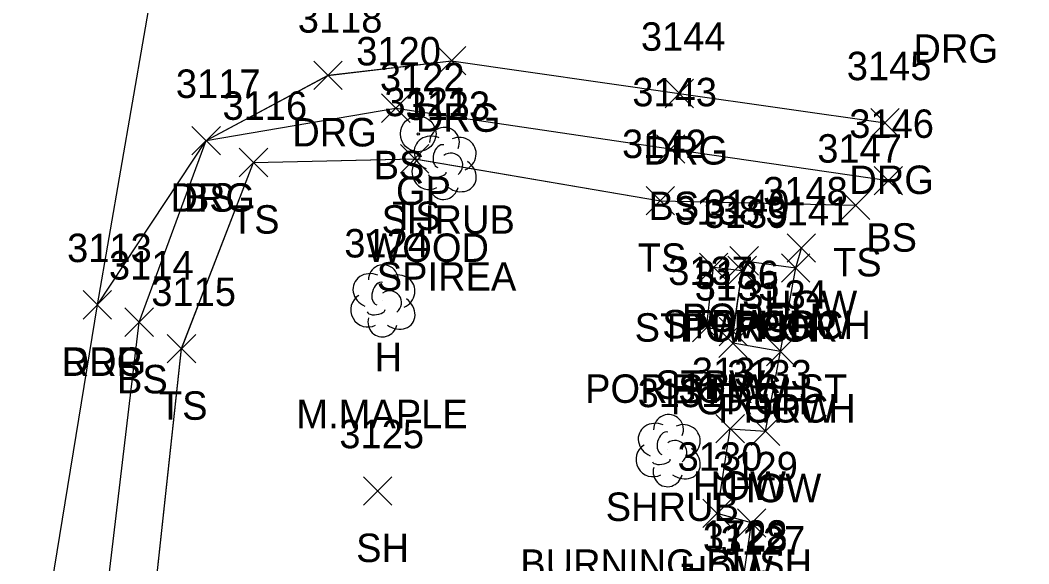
# Model space of a CAD drawing. Extents: x 1554668 to 1563881, y 831386 to 834374.
# Drawn here: x 1562326.2 to 1562397.1, y 833011.6 to 833049.8 of the extents above; entities that cross this region are included whole.
import ezdxf

# ---------------------------------------------------------------- set-up
doc = ezdxf.new("R2010")
doc.units = 0
for name, color, linetype in [('C_I', 7, 'Continuous'), ('L_A', 7, 'Continuous'), ('L_C', 7, 'Continuous'), ('L_I', 7, 'Continuous'), ('L_TIC', 7, 'Continuous'), ('LBC', 7, 'Continuous'), ('LBF', 7, 'Continuous'), ('LELB', 7, 'Continuous'), ('LSH', 7, 'Continuous'), ('LTD', 7, 'Continuous'), ('P_A', 7, 'Continuous'), ('P_I', 7, 'Continuous'), ('P_TIC', 7, 'Continuous'), ('PET', 7, 'Continuous'), ('R_A', 7, 'Continuous'), ('R_C', 7, 'Continuous'), ('R_I', 7, 'Continuous'), ('R_TIC', 7, 'Continuous'), ('RDG', 7, 'Continuous'), ('RGP', 7, 'Continuous')]:
    doc.layers.add(name, color=color, linetype=linetype)

msp = doc.modelspace()

# ---------------------------------------------------------------- linework, layer by layer
at = {"layer": 'L_TIC'}
for points in [[(1562351.645, 833042.623), (1562353.645, 833044.623)], [(1562353.645, 833042.623), (1562351.645, 833044.623)], [(1562338.315, 833040.338), (1562340.315, 833042.338)], [(1562340.315, 833040.338), (1562338.315, 833042.338)], [(1562370.953, 833039.751), (1562372.953, 833041.751)], [(1562372.953, 833039.751), (1562370.953, 833041.751)], [(1562352.966, 833039.056), (1562354.966, 833041.056)], [(1562354.966, 833039.056), (1562352.966, 833041.056)], [(1562341.647, 833038.798), (1562343.647, 833040.798)], [(1562343.647, 833038.798), (1562341.647, 833040.798)], [(1562386.252, 833037.529), (1562388.252, 833039.529)], [(1562388.252, 833037.529), (1562386.252, 833039.529)], [(1562370.232, 833036.114), (1562372.232, 833038.114)], [(1562372.232, 833036.114), (1562370.232, 833038.114)], [(1562383.95, 833035.789), (1562385.95, 833037.789)], [(1562385.95, 833035.789), (1562383.95, 833037.789)], [(1562380.14, 833032.785), (1562382.14, 833034.785)], [(1562382.14, 833032.785), (1562380.14, 833034.785)], [(1562376.122, 833031.884), (1562378.122, 833033.884)], [(1562378.122, 833031.884), (1562376.122, 833033.884)], [(1562373.972, 833031.433), (1562375.972, 833033.433)], [(1562375.972, 833031.433), (1562373.972, 833033.433)], [(1562375.975, 833031.204), (1562377.975, 833033.204)], [(1562377.975, 833031.204), (1562375.975, 833033.204)], [(1562375.975, 833031.204), (1562377.975, 833033.204)], [(1562377.975, 833031.204), (1562375.975, 833033.204)], [(1562379.744, 833031.387), (1562381.744, 833033.387)], [(1562381.744, 833031.387), (1562379.744, 833033.387)], [(1562379.744, 833031.387), (1562381.744, 833033.387)], [(1562381.744, 833031.387), (1562379.744, 833033.387)], [(1562333.613, 833027.571), (1562335.613, 833029.571)], [(1562335.613, 833027.571), (1562333.613, 833029.571)], [(1562373.478, 833027.184), (1562375.478, 833029.184)], [(1562375.478, 833027.184), (1562373.478, 833029.184)], [(1562375.358, 833026.903), (1562377.358, 833028.903)], [(1562377.358, 833026.903), (1562375.358, 833028.903)], [(1562375.358, 833026.903), (1562377.358, 833028.903)], [(1562377.358, 833026.903), (1562375.358, 833028.903)], [(1562336.588, 833025.713), (1562338.588, 833027.713)], [(1562338.588, 833025.713), (1562336.588, 833027.713)], [(1562375.339, 833026.093), (1562377.339, 833028.093)], [(1562377.339, 833026.093), (1562375.339, 833028.093)], [(1562378.681, 833025.516), (1562380.681, 833027.516)], [(1562380.681, 833025.516), (1562378.681, 833027.516)], [(1562378.681, 833025.516), (1562380.681, 833027.516)], [(1562380.681, 833025.516), (1562378.681, 833027.516)], [(1562375.137, 833020.084), (1562377.137, 833022.084)], [(1562377.137, 833020.084), (1562375.137, 833022.084)], [(1562377.615, 833019.915), (1562379.615, 833021.915)], [(1562379.615, 833019.915), (1562377.615, 833021.915)], [(1562350.368, 833015.711), (1562352.368, 833017.711)], [(1562352.368, 833015.711), (1562350.368, 833017.711)], [(1562374.22, 833014.13), (1562376.22, 833016.13)], [(1562376.22, 833014.13), (1562374.22, 833016.13)], [(1562376.642, 833013.459), (1562378.642, 833015.459)], [(1562378.642, 833013.459), (1562376.642, 833015.459)]]:
    msp.add_lwpolyline(points, dxfattribs=at)
at = {"layer": 'LBC'}
for points in [[(1562378.15, 833009.239), (1562376.909, 833009.438), (1562377.643, 833014.459), (1562375.22, 833015.13), (1562376.134, 833021.083), (1562378.615, 833020.915), (1562379.684, 833026.518), (1562380.743, 833032.387), (1562381.143, 833033.787)], [(1562378.15, 833009.239), (1562376.909, 833009.438), (1562377.643, 833014.459), (1562375.22, 833015.13), (1562376.134, 833021.083), (1562378.615, 833020.915), (1562379.684, 833026.518), (1562380.743, 833032.387), (1562381.143, 833033.787)], [(1562378.15, 833009.239), (1562376.909, 833009.438), (1562377.643, 833014.459), (1562375.22, 833015.13), (1562376.134, 833021.083), (1562378.615, 833020.915), (1562379.684, 833026.518), (1562380.743, 833032.387), (1562381.143, 833033.787)], [(1562378.154, 833009.24), (1562376.909, 833009.438), (1562377.642, 833014.459), (1562375.22, 833015.13), (1562376.137, 833021.084), (1562378.615, 833020.915), (1562379.681, 833026.516), (1562380.744, 833032.387), (1562381.14, 833033.785)]]:
    msp.add_lwpolyline(points, dxfattribs=at)
at = {"layer": 'LBF'}
for points in [[(1562376.359, 833027.903), (1562374.473, 833028.181), (1562374.969, 833032.431), (1562376.972, 833032.201)], [(1562376.359, 833027.903), (1562374.473, 833028.181), (1562374.969, 833032.431), (1562376.972, 833032.201)], [(1562376.359, 833027.903), (1562374.473, 833028.181), (1562374.969, 833032.431), (1562376.972, 833032.201)], [(1562376.358, 833027.903), (1562374.478, 833028.184), (1562374.972, 833032.433), (1562376.975, 833032.204)], [(1562379.684, 833026.518), (1562376.337, 833027.092), (1562376.359, 833027.903), (1562376.972, 833032.201), (1562377.118, 833032.881), (1562380.743, 833032.387)], [(1562379.684, 833026.518), (1562376.337, 833027.092), (1562376.359, 833027.903), (1562376.972, 833032.201), (1562377.118, 833032.881), (1562380.743, 833032.387)], [(1562379.684, 833026.518), (1562376.337, 833027.092), (1562376.359, 833027.903), (1562376.972, 833032.201), (1562377.118, 833032.881), (1562380.743, 833032.387)], [(1562379.681, 833026.516), (1562376.339, 833027.093), (1562376.358, 833027.903), (1562376.975, 833032.204), (1562377.122, 833032.884), (1562380.744, 833032.387)]]:
    msp.add_lwpolyline(points, dxfattribs=at)
at = {"layer": 'LELB'}
for points in [[(1562330.948, 832986.181), (1562330.333, 832992.465), (1562334.613, 833028.571), (1562339.315, 833041.338), (1562352.645, 833043.623), (1562371.953, 833040.751), (1562387.252, 833038.529)], [(1562330.948, 832986.176), (1562330.334, 832992.468), (1562334.613, 833028.567), (1562339.315, 833041.335), (1562352.643, 833043.62), (1562371.951, 833040.749), (1562387.252, 833038.529)], [(1562330.948, 832986.176), (1562330.334, 832992.468), (1562334.613, 833028.567), (1562339.315, 833041.335), (1562352.643, 833043.62), (1562371.951, 833040.749), (1562387.252, 833038.529)], [(1562330.948, 832986.176), (1562330.334, 832992.468), (1562334.613, 833028.567), (1562339.315, 833041.335), (1562352.643, 833043.62), (1562371.951, 833040.749), (1562387.252, 833038.529)], [(1562397.12, 832976.877), (1562362.884, 832982.961), (1562342.667, 832989.06), (1562335.967, 832990.605), (1562334.097, 832994.427), (1562337.587, 833026.709), (1562342.646, 833039.798), (1562353.968, 833040.061), (1562371.23, 833037.112), (1562384.952, 833036.79)], [(1562397.12, 832976.877), (1562362.884, 832982.961), (1562342.667, 832989.06), (1562335.967, 832990.605), (1562334.097, 832994.427), (1562337.587, 833026.709), (1562342.646, 833039.798), (1562353.968, 833040.061), (1562371.23, 833037.112), (1562384.952, 833036.79)], [(1562397.12, 832976.877), (1562362.884, 832982.961), (1562342.667, 832989.06), (1562335.967, 832990.605), (1562334.097, 832994.427), (1562337.587, 833026.709), (1562342.646, 833039.798), (1562353.968, 833040.061), (1562371.23, 833037.112), (1562384.952, 833036.79)], [(1562397.118, 832976.878), (1562362.885, 832982.961), (1562342.67, 832989.058), (1562335.966, 832990.607), (1562334.098, 832994.427), (1562337.588, 833026.713), (1562342.647, 833039.798), (1562353.966, 833040.056), (1562371.232, 833037.114), (1562384.95, 833036.789)]]:
    msp.add_lwpolyline(points, dxfattribs=at)
at = {"layer": 'LSH'}
for p, q in [((1562356.017, 833039.791), (1562356.017, 833039.791)), ((1562356.017, 833039.791), (1562356.017, 833039.791)), ((1562371.761, 833019.6), (1562371.761, 833019.6)), ((1562371.761, 833019.6), (1562371.761, 833019.6))]:
    msp.add_line(p, q, dxfattribs=at)
for centre in [(1562356.064, 833041.225), (1562371.807, 833021.034)]:
    msp.add_arc(centre, 1.047, 335.52715, 180.95627, dxfattribs=at)
for centre, major_axis, ratio, start_param, end_param in [((1562355.226, 833040.458), (1.21, -0.512), 0.895232, 1.570796, 4.712389), ((1562357.059, 833040.375), (-1.141, -0.483), 0.949671, 1.570796, 4.712389), ((1562355.809, 833040.249), (-0.208, -0.792), 0.645439, 3.141593, 6.283185), ((1562356.517, 833039.624), (-0.5, 0.667), 0.989748, 3.141593, 6.283185), ((1562354.934, 833039.083), (0.584, -1.042), 0.959034, 3.141593, 6.283185), ((1562357.017, 833038.958), (-1.09, 0.792), 0.841452, 1.570796, 4.712389), ((1562355.559, 833039.041), (-0.625, -0.083), 0.423636, 0, 3.141593), ((1562356.018, 833038.291), (0.265, 1.061), 0.942809, 1.570796, 4.712389), ((1562370.969, 833020.267), (1.21, -0.512), 0.895232, 1.570796, 4.712389), ((1562372.802, 833020.184), (-1.141, -0.483), 0.949671, 1.570796, 4.712389), ((1562371.552, 833020.058), (-0.208, -0.792), 0.645439, 3.141593, 6.283185), ((1562372.261, 833019.434), (-0.5, 0.667), 0.989748, 3.141593, 6.283185), ((1562370.677, 833018.892), (0.584, -1.042), 0.959034, 3.141593, 6.283185), ((1562372.761, 833018.767), (-1.09, 0.792), 0.841452, 1.570796, 4.712389), ((1562371.761, 833018.1), (0.265, 1.061), 0.942809, 1.570796, 4.712389), ((1562371.302, 833018.85), (-0.625, -0.083), 0.423636, 0, 3.141593)]:
    msp.add_ellipse(centre, major_axis=major_axis, ratio=ratio, start_param=start_param, end_param=end_param, dxfattribs=at)
at = {"layer": 'LTD'}
msp.add_line((1562351.719, 833030.123), (1562351.719, 833030.123), dxfattribs=at)
msp.add_line((1562351.719, 833030.123), (1562351.719, 833030.123), dxfattribs=at)
msp.add_arc((1562351.766, 833031.557), 1.047, 335.52715, 180.95627, dxfattribs=at)
for centre, major_axis, ratio, start_param, end_param in [((1562350.927, 833030.789), (1.21, -0.512), 0.895232, 1.570796, 4.712389), ((1562352.76, 833030.706), (-1.141, -0.483), 0.949671, 1.570796, 4.712389), ((1562351.51, 833030.581), (-0.208, -0.792), 0.645439, 3.141593, 6.283185), ((1562350.636, 833029.414), (0.584, -1.042), 0.959034, 3.141593, 6.283185), ((1562352.219, 833029.956), (-0.5, 0.667), 0.989748, 3.141593, 6.283185), ((1562352.719, 833029.29), (-1.09, 0.792), 0.841452, 1.570796, 4.712389), ((1562351.261, 833029.373), (-0.625, -0.083), 0.423636, 0, 3.141593), ((1562351.719, 833028.623), (0.265, 1.061), 0.942809, 1.570796, 4.712389)]:
    msp.add_ellipse(centre, major_axis=major_axis, ratio=ratio, start_param=start_param, end_param=end_param, dxfattribs=at)
at = {"layer": 'P_TIC'}
for points in [[(1562330.672, 833028.796), (1562332.672, 833030.796)], [(1562332.672, 833028.796), (1562330.672, 833030.796)]]:
    msp.add_lwpolyline(points, dxfattribs=at)
at = {"layer": 'PET'}
for points in [[(1562293.2, 832810.286), (1562300.396, 832850.568), (1562308.055, 832893.341), (1562311.287, 832911.514), (1562317.744, 832948.774), (1562319.194, 832956.227), (1562322.7, 832975.05), (1562324.671, 832987.025), (1562331.672, 833029.796), (1562339.066, 833072.416), (1562343.078, 833095.98), (1562348.142, 833128.239), (1562354.649, 833163.69), (1562361.17, 833205.426), (1562366.308, 833231.661), (1562371.389, 833259.656), (1562381.749, 833322.062), (1562383.966, 833334.665), (1562387.156, 833355.182), (1562390.312, 833375.983), (1562393.977, 833397.668)], [(1562293.205, 832810.287), (1562300.398, 832850.573), (1562308.061, 832893.345), (1562311.291, 832911.518), (1562317.744, 832948.775), (1562319.194, 832956.226), (1562322.701, 832975.053), (1562324.671, 832987.025), (1562331.672, 833029.797), (1562339.066, 833072.413), (1562343.078, 833095.98), (1562348.141, 833128.239), (1562354.651, 833163.692), (1562361.172, 833205.429), (1562366.308, 833231.663), (1562371.39, 833259.659), (1562381.75, 833322.061), (1562383.966, 833334.667), (1562387.156, 833355.187), (1562390.311, 833375.989), (1562393.977, 833397.67)], [(1562293.205, 832810.287), (1562300.398, 832850.573), (1562308.061, 832893.345), (1562311.291, 832911.518), (1562317.744, 832948.775), (1562319.194, 832956.226), (1562322.701, 832975.053), (1562324.671, 832987.025), (1562331.672, 833029.797), (1562339.066, 833072.413), (1562343.078, 833095.98), (1562348.141, 833128.239), (1562354.651, 833163.692), (1562361.172, 833205.429), (1562366.308, 833231.663), (1562371.39, 833259.659), (1562381.75, 833322.061), (1562383.966, 833334.667), (1562387.156, 833355.187), (1562390.311, 833375.989), (1562393.977, 833397.67)], [(1562293.205, 832810.287), (1562300.398, 832850.573), (1562308.061, 832893.345), (1562311.291, 832911.518), (1562317.744, 832948.775), (1562319.194, 832956.226), (1562322.701, 832975.053), (1562324.671, 832987.025), (1562331.672, 833029.797), (1562339.066, 833072.413), (1562343.078, 833095.98), (1562348.141, 833128.239), (1562354.651, 833163.692), (1562361.172, 833205.429), (1562366.308, 833231.663), (1562371.39, 833259.659), (1562381.75, 833322.061), (1562383.966, 833334.667), (1562387.156, 833355.187), (1562390.311, 833375.989), (1562393.977, 833397.67)]]:
    msp.add_lwpolyline(points, dxfattribs=at)
at = {"layer": 'R_TIC'}
for points in [[(1562355.561, 833045.956), (1562357.561, 833047.956)], [(1562357.561, 833045.956), (1562355.561, 833047.956)], [(1562346.88, 833044.928), (1562348.88, 833046.928)], [(1562348.88, 833044.928), (1562346.88, 833046.928)], [(1562371.558, 833043.654), (1562373.558, 833045.654)], [(1562373.558, 833043.654), (1562371.558, 833045.654)], [(1562386.021, 833041.585), (1562388.021, 833043.585)], [(1562388.021, 833041.585), (1562386.021, 833043.585)], [(1562338.315, 833040.338), (1562340.315, 833042.338)], [(1562340.315, 833040.338), (1562338.315, 833042.338)], [(1562330.672, 833028.796), (1562332.672, 833030.796)], [(1562332.672, 833028.796), (1562330.672, 833030.796)]]:
    msp.add_lwpolyline(points, dxfattribs=at)
at = {"layer": 'RDG'}
for points in [[(1562331.672, 833029.796), (1562339.315, 833041.338), (1562347.88, 833045.928), (1562356.561, 833046.956), (1562372.558, 833044.654), (1562387.021, 833042.585)], [(1562331.672, 833029.797), (1562339.315, 833041.335), (1562347.878, 833045.923), (1562356.56, 833046.954), (1562372.558, 833044.654), (1562387.02, 833042.585)], [(1562331.672, 833029.797), (1562339.315, 833041.335), (1562347.878, 833045.923), (1562356.56, 833046.954), (1562372.558, 833044.654), (1562387.02, 833042.585)], [(1562331.672, 833029.797), (1562339.315, 833041.335), (1562347.878, 833045.923), (1562356.56, 833046.954), (1562372.558, 833044.654), (1562387.02, 833042.585)]]:
    msp.add_lwpolyline(points, dxfattribs=at)
at = {"layer": 'RGP'}
msp.add_line((1562354.218, 833041.81), (1562354.218, 833041.81), dxfattribs=at)
for radius in [1.25, 0.0833]:
    msp.add_circle((1562354.218, 833041.81), radius, dxfattribs=at)

# ---------------------------------------------------------------- texts
at = {"layer": 'C_I'}
msp.add_text('1723', height=2, dxfattribs=at).set_placement((1562374.215, 833012.65))
at = {"layer": 'L_A'}
for s, p in [('BS', (1562351.086, 833038.623)), ('BS', (1562337.756, 833036.338)), ('BS', (1562370.394, 833035.751)), ('TS', (1562341.056, 833034.798)), ('SHRUB', (1562351.647, 833034.791)), ('TS', (1562352.376, 833035.056)), ('BS', (1562385.693, 833033.529)), ('TS', (1562369.641, 833032.114)), ('TS', (1562383.36, 833031.789)), ('HOW', (1562378.526, 833028.785)), ('PORCH', (1562372.744, 833027.884)), ('STPW POR', (1562369.424, 833027.204)), ('STPW', (1562371.366, 833027.433)), ('PORCH', (1562372.597, 833027.204)), ('PORCH', (1562376.366, 833027.387)), ('HOW', (1562378.129, 833027.387)), ('H', (1562351.152, 833025.123)), ('BS', (1562333.054, 833023.571)), ('POR STPW ST', (1562365.94, 833022.903)), ('STPW', (1562370.871, 833023.184)), ('PORCH', (1562371.98, 833022.903)), ('PORCH', (1562371.961, 833022.093)), ('TS', (1562335.998, 833021.713)), ('PORCH', (1562375.303, 833021.516)), ('HOW', (1562377.067, 833021.516)), ('HOW', (1562373.522, 833016.084)), ('HOW', (1562376.001, 833015.915)), ('SHRUB', (1562367.39, 833014.6)), ('SH', (1562349.856, 833011.711)), ('HOW', (1562372.605, 833010.13))]:
    msp.add_text(s, height=2, dxfattribs=at).set_placement(p)
at = {"layer": 'L_C'}
for s, p in [('SPIREA', (1562351.301, 833030.791)), ('M.MAPLE', (1562345.656, 833021.123)), ('BURNING BUSH', (1562361.383, 833010.6))]:
    msp.add_text(s, height=2, dxfattribs=at).set_placement(p)
at = {"layer": 'L_I'}
for s, p in [('3120', (1562349.865, 833046.623)), ('3117', (1562337.189, 833044.338)), ('3143', (1562369.26, 833043.751)), ('3116', (1562340.466, 833042.798)), ('3121', (1562351.84, 833043.056)), ('3123', (1562353.324, 833042.791)), ('3146', (1562384.504, 833041.529)), ('3142', (1562368.539, 833040.114)), ('3147', (1562382.257, 833039.789)), ('3148', (1562378.447, 833036.785)), ('3138', (1562372.279, 833035.433)), ('3140', (1562374.342, 833035.884)), ('3141', (1562378.618, 833035.387)), ('3141', (1562378.618, 833035.387)), ('3139', (1562374.275, 833035.204)), ('3139', (1562374.275, 833035.204)), ('3124', (1562349.026, 833033.123)), ('3114', (1562332.487, 833031.571)), ('3137', (1562371.785, 833031.184)), ('3136', (1562373.61, 833030.903)), ('3136', (1562373.61, 833030.903)), ('3115', (1562335.462, 833029.713)), ('3135', (1562373.646, 833030.093)), ('3134', (1562376.988, 833029.516)), ('3134', (1562376.988, 833029.516)), ('3132', (1562373.444, 833024.084)), ('3133', (1562375.922, 833023.915)), ('3131', (1562369.635, 833022.6)), ('3125', (1562348.675, 833019.711)), ('3130', (1562372.44, 833018.13)), ('3129', (1562374.941, 833017.459)), ('3128', (1562374.216, 833012.438)), ('3127', (1562375.461, 833012.24)), ('3127', (1562375.461, 833012.24))]:
    msp.add_text(s, height=2, dxfattribs=at).set_placement(p)
at = {"layer": 'P_A'}
msp.add_text('RDP', height=2, dxfattribs=at).set_placement((1562329.161, 833024.796))
at = {"layer": 'P_I'}
msp.add_text('3113', height=2, dxfattribs=at).set_placement((1562329.546, 833032.796))
at = {"layer": 'R_A'}
for s, p in [('DRG', (1562389.014, 833046.811)), ('DRG', (1562354.049, 833041.956)), ('DRG', (1562345.368, 833040.928)), ('DRG', (1562370.046, 833039.654)), ('DRG', (1562384.509, 833037.585)), ('GP', (1562352.651, 833036.81)), ('DRG', (1562336.804, 833036.338)), ('DRG', (1562329.161, 833024.796))]:
    msp.add_text(s, height=2, dxfattribs=at).set_placement(p)
at = {"layer": 'R_C'}
msp.add_text('WOOD', height=2, dxfattribs=at).set_placement((1562350.572, 833032.81))
at = {"layer": 'R_I'}
for s, p in [('3118', (1562345.754, 833048.928)), ('3144', (1562369.865, 833047.654)), ('3145', (1562384.328, 833045.585)), ('3122', (1562351.525, 833044.81)), ('3117', (1562337.189, 833044.338)), ('3113', (1562329.546, 833032.796))]:
    msp.add_text(s, height=2, dxfattribs=at).set_placement(p)

doc.saveas('drawing.dxf')
